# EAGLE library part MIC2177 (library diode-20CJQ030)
MICREL's MIC2177 2.5A Syncronous BUck Regulator General Description: The Micrel MIC2177 is a 200kHz synchronous buck (stepdown) switching regulator designed for high-efficiency, battery- powered applications. The MIC2177 operates from a 4.5V to 16.5V input and features internal power MOSFETs that can supply up to 2.5A output current. It can operate with a maximum duty cycle of 100% for use in low-dropout conditions. It also features a shutdown mode that reduces quiescent current to less than 5µA. The MIC2177 achieves high efficiency over a wide output current range by switching between PWM and skip mode. Operating mode is automatically selected according to output conditions. Switching frequency is preset to 200kHz and can be synchronized to an external clock signal of up to 300kHz. The MIC2177 uses current-mode control with internal current sensing. Current-mode control provides superior line regulation and makes the regulator control loop easy to compensate. The output is protected with pulse-by-pulse current limiting and thermal shutdown. Undervoltage lockout turns the output off when the input voltage is less than 4.5V. The MIC2177 is packaged in a 20-lead wide power SO package with an operating temperature range of -40°C to +85°C. See the MIC2178 for externally selected PWM or skip-mode operation. Features: 4.5V to 16.5V input voltage range Dual-mode operation for high efficiency (up to 96%) PWM mode for > 200mA load current Skip mode for Applications: High-efficiency,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
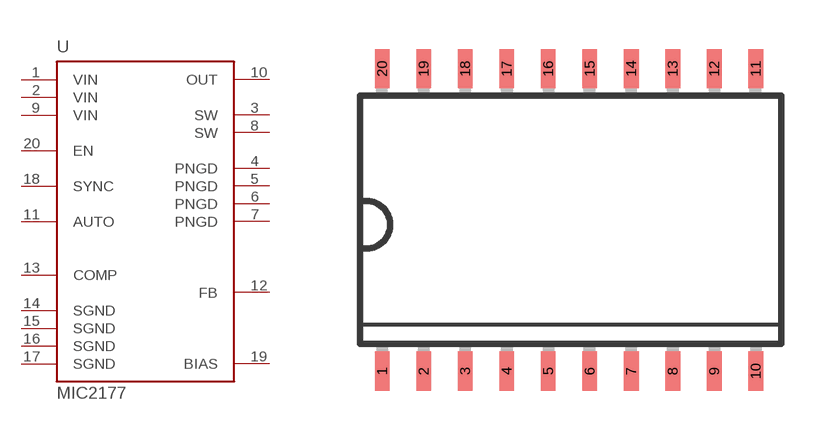
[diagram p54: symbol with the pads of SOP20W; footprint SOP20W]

Designator prefix U

## MIC2177  [SOP20W]
1  VIN  pwr
2  VIN  pwr
3  SW  out
4  PNGD  pwr
5  PNGD  pwr
6  PNGD  pwr
7  PNGD  pwr
8  SW  out
9  VIN  pwr
10  OUT  out
11  AUTO  in
12  FB  in
13  COMP  out
14  SGND  pwr
15  SGND  pwr
16  SGND  pwr
17  SGND  pwr
18  SYNC  in
19  BIAS
20  EN  in

## Footprint SOP20W (pad centres in mm)
SOP20 Wide, Used in Micrel 2177
smd 0.45 x 1.2: 1 -5.715,-4.58; 2 -4.445,-4.58; 3 -3.175,-4.58; 4 -1.905,-4.58; 5 -0.635,-4.58; 6 0.635,-4.58; 7 1.905,-4.58; 8 3.175,-4.58; 9 4.445,-4.58; 10 5.715,-4.58; 11 5.715,4.68; 12 4.445,4.68; 13 3.175,4.68; 14 1.905,4.68; 15 0.635,4.68; 16 -0.635,4.68; 17 -1.905,4.68; 18 -3.175,4.68; 19 -4.445,4.68; 20 -5.715,4.68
